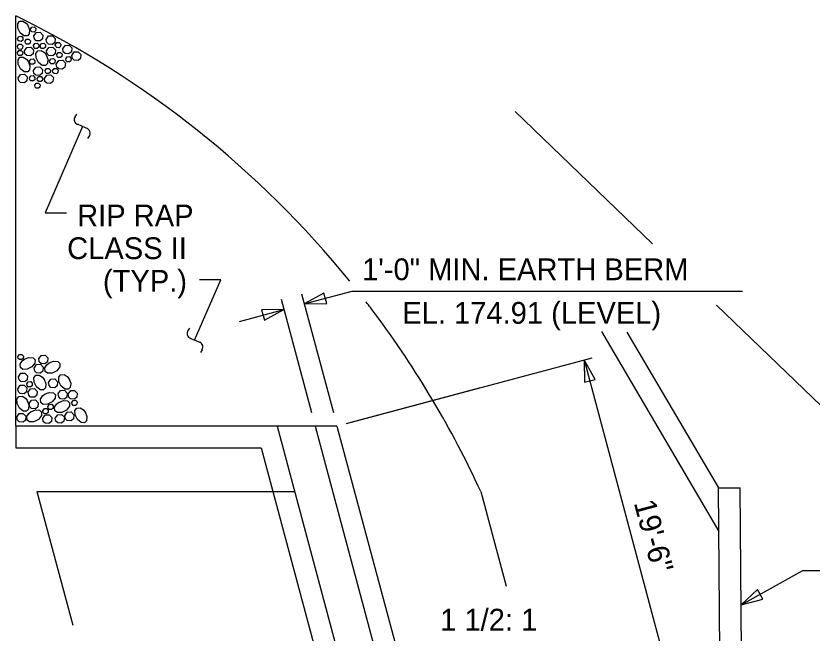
# Model space of a CAD drawing. Extents: x -20 to 509, y -659 to 21.
# Drawn here: x 57.47 to 94.05, y -95.57 to -67.25 of the extents above; entities that cross this region are included whole.
import ezdxf

# ---------------------------------------------------------------- set-up
doc = ezdxf.new("R2010")
doc.units = 0
for name, color, linetype in [('Arrowhead Terminators CELL', 7, 'Continuous'), ('Dimension Lines', 7, 'Continuous'), ('Exist Hydro Stream or Body of Water', 7, 'Continuous'), ('Exist Structure Major Bridge Seam', 7, 'Continuous'), ('Mis Object Lines', 7, 'Continuous'), ('Mis Object Lines Hidden', 7, 'Continuous'), ('Miscellaneous Lines CELL', 7, 'Continuous'), ('Sup Concrete Girder Lines', 7, 'Continuous'), ('Text', 7, 'Continuous')]:
    doc.layers.add(name, color=color, linetype=linetype)

msp = doc.modelspace()

# ---------------------------------------------------------------- linework, layer by layer
at = {"layer": 'Arrowhead Terminators CELL'}
for p, q in [((60.197, -71.878), (60.272, -71.752)), ((60.709, -72.397), (60.303, -72.221)), ((60.778, -72.876), (60.838, -72.784)), ((65.442, -81.57), (65.382, -81.662)), ((65.512, -82.049), (65.918, -82.224)), ((66.024, -82.567), (65.949, -82.694))]:
    msp.add_line(p, q, dxfattribs=at)
for points in [[(70.722, -80.467), (71.753, -80.449), (71.624, -79.966)], [(69.789, -80.717), (68.759, -80.734), (68.888, -81.217)], [(83.578, -83.03), (83.58, -83.114), (83.619, -83.103)], [(83.578, -83.03), (83.596, -84.061), (84.079, -83.931)], [(90.793, -94.277), (91.789, -94.011), (91.546, -93.574)]]:
    msp.add_lwpolyline(points, close=True, dxfattribs=at)
for centre, radius, start, end in [((60.373, -72.014), 0.221, 142.4705, 250.7561), ((60.637, -72.634), 0.249, 323.4021, 73.201), ((65.584, -81.811), 0.249, 143.4021, 253.201), ((65.847, -82.432), 0.221, 322.4705, 70.7561)]:
    msp.add_arc(centre, radius, start, end, dxfattribs=at)
at = {"layer": 'Dimension Lines'}
for p, q in [((60.536, -72.316), (58.823, -76.282)), ((58.823, -76.282), (59.794, -76.282)), ((65.685, -82.129), (66.883, -79.356)), ((66.883, -79.356), (65.911, -79.356)), ((70.598, -80.002), (72.058, -85.451)), ((70.722, -80.467), (72.926, -79.876)), ((72.926, -79.876), (90.848, -79.876)), ((69.665, -80.252), (71.057, -85.448)), ((67.742, -81.265), (69.789, -80.717)), ((72.661, -85.956), (83.942, -82.933)), ((83.578, -83.03), (88.262, -100.509)), ((72.875, -85.898), (78.772, -84.318)), ((90.793, -94.277), (93.629, -92.706)), ((93.629, -92.706), (95.304, -92.706))]:
    msp.add_line(p, q, dxfattribs=at)
at = {"layer": 'Exist Hydro Stream or Body of Water'}
for points in [[(86.72, -77.7), (80.409, -71.639)], [(97.738, -91.292), (97.285, -87.847), (89.653, -80.517)]]:
    msp.add_lwpolyline(points, dxfattribs=at)
at = {"layer": 'Exist Structure Major Bridge Seam'}
for p, q in [((84.37, -81.73), (89.763, -90.904)), ((85.546, -81.757), (89.745, -88.901)), ((89.745, -88.901), (90.745, -88.901)), ((89.892, -105.444), (89.745, -88.901)), ((90.898, -106.065), (90.745, -88.901))]:
    msp.add_line(p, q, dxfattribs=at)
at = {"layer": 'Mis Object Lines'}
for p, q in [((69.475, -86.072), (79.344, -122.906)), ((71.225, -86.072), (81.094, -122.906)), ((72.225, -86.072), (82.094, -122.906)), ((58.438, -89.072), (60.083, -95.211)), ((58.438, -89.072), (70.278, -89.072))]:
    msp.add_line(p, q, dxfattribs=at)
for points in [[(72.225, -86.072), (57.475, -86.072), (57.475, -87.072), (68.742, -87.072)], [(68.742, -87.072), (69.278, -89.072)]]:
    msp.add_lwpolyline(points, dxfattribs=at)
at = {"layer": 'Mis Object Lines Hidden'}
msp.add_lwpolyline([(69.278, -89.072), (77.54, -119.906)], dxfattribs=at)
at = {"layer": 'Miscellaneous Lines CELL'}
for points in [[(58.022, -67.668), (58.105, -67.878), (58.088, -68.071), (58.001, -68.162), (57.845, -68.159), (57.667, -68.02), (57.56, -67.806), (57.557, -67.603), (57.637, -67.49), (57.799, -67.479), (57.943, -67.571), (58.027, -67.677)], [(58.022, -67.668), (58.105, -67.878), (58.088, -68.071), (58.001, -68.162), (57.845, -68.159), (57.667, -68.02), (57.56, -67.806), (57.557, -67.603), (57.637, -67.49), (57.799, -67.479), (57.943, -67.571), (58.027, -67.677)], [(58.14, -67.85), (58.207, -67.755), (58.314, -67.748), (58.389, -67.826), (58.378, -67.934), (58.312, -67.989), (58.206, -67.982), (58.156, -67.933), (58.14, -67.85)], [(58.14, -67.85), (58.207, -67.755), (58.314, -67.748), (58.389, -67.826), (58.378, -67.934), (58.312, -67.989), (58.206, -67.982), (58.156, -67.933), (58.14, -67.85)], [(58.302, -68.163), (58.414, -68.004), (58.593, -67.993), (58.717, -68.122), (58.699, -68.303), (58.589, -68.395), (58.412, -68.382), (58.329, -68.301), (58.302, -68.163)], [(58.302, -68.163), (58.414, -68.004), (58.593, -67.993), (58.717, -68.122), (58.699, -68.303), (58.589, -68.395), (58.412, -68.382), (58.329, -68.301), (58.302, -68.163)], [(57.55, -68.279), (57.617, -68.183), (57.725, -68.177), (57.799, -68.255), (57.789, -68.363), (57.722, -68.418), (57.616, -68.411), (57.566, -68.362), (57.55, -68.279)], [(57.55, -68.279), (57.617, -68.183), (57.725, -68.177), (57.799, -68.255), (57.789, -68.363), (57.722, -68.418), (57.616, -68.411), (57.566, -68.362), (57.55, -68.279)], [(57.897, -68.407), (57.965, -68.311), (58.072, -68.305), (58.147, -68.382), (58.136, -68.491), (58.07, -68.546), (57.964, -68.538), (57.914, -68.49), (57.897, -68.407)], [(57.897, -68.407), (57.965, -68.311), (58.072, -68.305), (58.147, -68.382), (58.136, -68.491), (58.07, -68.546), (57.964, -68.538), (57.914, -68.49), (57.897, -68.407)], [(58.865, -68.326), (58.977, -68.166), (59.156, -68.156), (59.28, -68.285), (59.262, -68.466), (59.152, -68.558), (58.975, -68.545), (58.892, -68.464), (58.865, -68.326)], [(58.865, -68.326), (58.977, -68.166), (59.156, -68.156), (59.28, -68.285), (59.262, -68.466), (59.152, -68.558), (58.975, -68.545), (58.892, -68.464), (58.865, -68.326)], [(57.54, -68.64), (57.607, -68.544), (57.714, -68.538), (57.789, -68.615), (57.778, -68.724), (57.712, -68.779), (57.606, -68.771), (57.556, -68.723), (57.54, -68.64)], [(57.54, -68.64), (57.607, -68.544), (57.714, -68.538), (57.789, -68.615), (57.778, -68.724), (57.712, -68.779), (57.606, -68.771), (57.556, -68.723), (57.54, -68.64)], [(57.863, -68.847), (57.975, -68.688), (58.154, -68.678), (58.278, -68.806), (58.26, -68.987), (58.15, -69.079), (57.973, -69.066), (57.89, -68.986), (57.863, -68.847)], [(57.863, -68.847), (57.975, -68.688), (58.154, -68.678), (58.278, -68.806), (58.26, -68.987), (58.15, -69.079), (57.973, -69.066), (57.89, -68.986), (57.863, -68.847)], [(58.283, -68.602), (58.35, -68.506), (58.458, -68.5), (58.532, -68.577), (58.522, -68.686), (58.455, -68.741), (58.349, -68.733), (58.299, -68.685), (58.283, -68.602)], [(58.283, -68.602), (58.35, -68.506), (58.458, -68.5), (58.532, -68.577), (58.522, -68.686), (58.455, -68.741), (58.349, -68.733), (58.299, -68.685), (58.283, -68.602)], [(58.587, -68.602), (58.654, -68.506), (58.762, -68.5), (58.836, -68.577), (58.826, -68.686), (58.759, -68.741), (58.653, -68.733), (58.603, -68.685), (58.587, -68.602)], [(58.587, -68.602), (58.654, -68.506), (58.762, -68.5), (58.836, -68.577), (58.826, -68.686), (58.759, -68.741), (58.653, -68.733), (58.603, -68.685), (58.587, -68.602)], [(58.882, -68.847), (58.994, -68.688), (59.173, -68.678), (59.297, -68.806), (59.279, -68.987), (59.169, -69.079), (58.992, -69.066), (58.909, -68.986), (58.882, -68.847)], [(58.882, -68.847), (58.994, -68.688), (59.173, -68.678), (59.297, -68.806), (59.279, -68.987), (59.169, -69.079), (58.992, -69.066), (58.909, -68.986), (58.882, -68.847)], [(59.285, -68.566), (59.352, -68.47), (59.459, -68.464), (59.534, -68.541), (59.523, -68.65), (59.457, -68.705), (59.351, -68.697), (59.301, -68.649), (59.285, -68.566)], [(59.285, -68.566), (59.352, -68.47), (59.459, -68.464), (59.534, -68.541), (59.523, -68.65), (59.457, -68.705), (59.351, -68.697), (59.301, -68.649), (59.285, -68.566)], [(59.624, -68.758), (59.737, -68.598), (59.915, -68.588), (60.04, -68.717), (60.022, -68.898), (59.911, -68.99), (59.735, -68.977), (59.652, -68.896), (59.625, -68.758)], [(59.624, -68.758), (59.737, -68.598), (59.915, -68.588), (60.04, -68.717), (60.022, -68.898), (59.911, -68.99), (59.735, -68.977), (59.652, -68.896), (59.625, -68.758)], [(57.54, -68.93), (57.607, -68.834), (57.714, -68.828), (57.789, -68.905), (57.778, -69.014), (57.712, -69.069), (57.606, -69.061), (57.556, -69.013), (57.54, -68.93)], [(57.54, -68.93), (57.607, -68.834), (57.714, -68.828), (57.789, -68.905), (57.778, -69.014), (57.712, -69.069), (57.606, -69.061), (57.556, -69.013), (57.54, -68.93)], [(58.86, -69.028), (58.943, -69.237), (58.927, -69.43), (58.84, -69.521), (58.683, -69.519), (58.506, -69.38), (58.398, -69.165), (58.395, -68.963), (58.476, -68.849), (58.637, -68.838), (58.781, -68.93), (58.865, -69.036)], [(58.86, -69.028), (58.943, -69.237), (58.927, -69.43), (58.84, -69.521), (58.683, -69.519), (58.506, -69.38), (58.398, -69.165), (58.395, -68.963), (58.476, -68.849), (58.637, -68.838), (58.781, -68.93), (58.865, -69.036)], [(59.349, -69.021), (59.416, -68.926), (59.524, -68.92), (59.598, -68.997), (59.588, -69.105), (59.521, -69.161), (59.415, -69.153), (59.365, -69.105), (59.349, -69.021)], [(59.349, -69.021), (59.416, -68.926), (59.524, -68.92), (59.598, -68.997), (59.588, -69.105), (59.521, -69.161), (59.415, -69.153), (59.365, -69.105), (59.349, -69.021)], [(59.76, -69.217), (59.827, -69.121), (59.935, -69.115), (60.009, -69.192), (59.998, -69.301), (59.932, -69.356), (59.826, -69.348), (59.776, -69.3), (59.76, -69.217)], [(59.76, -69.217), (59.827, -69.121), (59.935, -69.115), (60.009, -69.192), (59.998, -69.301), (59.932, -69.356), (59.826, -69.348), (59.776, -69.3), (59.76, -69.217)], [(60.04, -69.059), (60.152, -68.9), (60.331, -68.89), (60.456, -69.019), (60.438, -69.199), (60.327, -69.291), (60.15, -69.279), (60.067, -69.198), (60.04, -69.059)], [(60.04, -69.059), (60.152, -68.9), (60.331, -68.89), (60.456, -69.019), (60.438, -69.199), (60.327, -69.291), (60.15, -69.279), (60.067, -69.198), (60.04, -69.059)], [(58.037, -69.324), (58.12, -69.534), (58.103, -69.726), (58.016, -69.818), (57.86, -69.815), (57.682, -69.676), (57.575, -69.461), (57.571, -69.259), (57.652, -69.145), (57.813, -69.134), (57.958, -69.227), (58.042, -69.333)], [(58.037, -69.324), (58.12, -69.534), (58.103, -69.726), (58.016, -69.818), (57.86, -69.815), (57.682, -69.676), (57.575, -69.461), (57.571, -69.259), (57.652, -69.145), (57.813, -69.134), (57.958, -69.227), (58.042, -69.333)], [(58.1, -69.323), (58.167, -69.228), (58.274, -69.222), (58.349, -69.299), (58.338, -69.407), (58.272, -69.462), (58.166, -69.455), (58.116, -69.406), (58.1, -69.323)], [(58.1, -69.323), (58.167, -69.228), (58.274, -69.222), (58.349, -69.299), (58.338, -69.407), (58.272, -69.462), (58.166, -69.455), (58.116, -69.406), (58.1, -69.323)], [(59.024, -69.305), (59.091, -69.21), (59.199, -69.204), (59.273, -69.281), (59.263, -69.389), (59.196, -69.444), (59.09, -69.437), (59.04, -69.388), (59.024, -69.305)], [(59.024, -69.305), (59.091, -69.21), (59.199, -69.204), (59.273, -69.281), (59.263, -69.389), (59.196, -69.444), (59.09, -69.437), (59.04, -69.388), (59.024, -69.305)], [(59.331, -69.452), (59.443, -69.292), (59.622, -69.282), (59.746, -69.411), (59.728, -69.592), (59.617, -69.684), (59.441, -69.671), (59.358, -69.59), (59.331, -69.452)], [(59.331, -69.452), (59.443, -69.292), (59.622, -69.282), (59.746, -69.411), (59.728, -69.592), (59.617, -69.684), (59.441, -69.671), (59.358, -69.59), (59.331, -69.452)], [(58.276, -69.751), (58.388, -69.591), (58.567, -69.581), (58.691, -69.71), (58.673, -69.891), (58.562, -69.983), (58.386, -69.97), (58.303, -69.889), (58.276, -69.751)], [(58.276, -69.751), (58.388, -69.591), (58.567, -69.581), (58.691, -69.71), (58.673, -69.891), (58.562, -69.983), (58.386, -69.97), (58.303, -69.889), (58.276, -69.751)], [(58.815, -69.753), (58.883, -69.657), (58.99, -69.651), (59.065, -69.729), (59.054, -69.837), (58.987, -69.892), (58.881, -69.885), (58.832, -69.836), (58.815, -69.753)], [(58.815, -69.753), (58.883, -69.657), (58.99, -69.651), (59.065, -69.729), (59.054, -69.837), (58.987, -69.892), (58.881, -69.885), (58.832, -69.836), (58.815, -69.753)], [(59.16, -69.758), (59.227, -69.662), (59.335, -69.656), (59.409, -69.733), (59.398, -69.842), (59.332, -69.897), (59.226, -69.889), (59.176, -69.841), (59.16, -69.758)], [(59.16, -69.758), (59.227, -69.662), (59.335, -69.656), (59.409, -69.733), (59.398, -69.842), (59.332, -69.897), (59.226, -69.889), (59.176, -69.841), (59.16, -69.758)], [(57.578, -70.089), (57.69, -69.929), (57.869, -69.919), (57.993, -70.048), (57.975, -70.229), (57.865, -70.321), (57.688, -70.308), (57.605, -70.227), (57.578, -70.089)], [(57.578, -70.089), (57.69, -69.929), (57.869, -69.919), (57.993, -70.048), (57.975, -70.229), (57.865, -70.321), (57.688, -70.308), (57.605, -70.227), (57.578, -70.089)], [(58.1, -70.088), (58.167, -69.993), (58.274, -69.986), (58.349, -70.064), (58.338, -70.172), (58.272, -70.227), (58.166, -70.22), (58.116, -70.171), (58.1, -70.088)], [(58.1, -70.088), (58.167, -69.993), (58.274, -69.986), (58.349, -70.064), (58.338, -70.172), (58.272, -70.227), (58.166, -70.22), (58.116, -70.171), (58.1, -70.088)], [(58.454, -70.121), (58.521, -70.026), (58.628, -70.02), (58.703, -70.097), (58.692, -70.205), (58.626, -70.261), (58.52, -70.253), (58.47, -70.205), (58.454, -70.121)], [(58.454, -70.121), (58.521, -70.026), (58.628, -70.02), (58.703, -70.097), (58.692, -70.205), (58.626, -70.261), (58.52, -70.253), (58.47, -70.205), (58.454, -70.121)], [(58.78, -70.119), (58.892, -69.959), (59.071, -69.949), (59.195, -70.078), (59.177, -70.259), (59.067, -70.35), (58.89, -70.338), (58.807, -70.257), (58.78, -70.119)], [(58.78, -70.119), (58.892, -69.959), (59.071, -69.949), (59.195, -70.078), (59.177, -70.259), (59.067, -70.35), (58.89, -70.338), (58.807, -70.257), (58.78, -70.119)], [(58.339, -70.426), (58.406, -70.33), (58.514, -70.324), (58.588, -70.401), (58.578, -70.51), (58.511, -70.565), (58.405, -70.557), (58.355, -70.509), (58.339, -70.426)], [(58.339, -70.426), (58.406, -70.33), (58.514, -70.324), (58.588, -70.401), (58.578, -70.51), (58.511, -70.565), (58.405, -70.557), (58.355, -70.509), (58.339, -70.426)], [(57.567, -82.882), (57.635, -82.787), (57.742, -82.78), (57.817, -82.858), (57.806, -82.966), (57.739, -83.021), (57.633, -83.014), (57.584, -82.965), (57.567, -82.882)], [(57.858, -83.005), (58.067, -82.922), (58.26, -82.938), (58.351, -83.025), (58.348, -83.182), (58.21, -83.359), (57.995, -83.467), (57.793, -83.47), (57.679, -83.389), (57.668, -83.228), (57.76, -83.084), (57.866, -83)], [(58.522, -82.985), (58.634, -82.825), (58.813, -82.815), (58.937, -82.944), (58.919, -83.125), (58.808, -83.216), (58.632, -83.204), (58.549, -83.123), (58.522, -82.985)], [(58.311, -83.406), (58.423, -83.247), (58.602, -83.237), (58.726, -83.366), (58.708, -83.546), (58.598, -83.638), (58.421, -83.625), (58.338, -83.545), (58.311, -83.406)], [(58.996, -83.174), (59.206, -83.091), (59.399, -83.108), (59.49, -83.195), (59.487, -83.351), (59.348, -83.529), (59.134, -83.636), (58.931, -83.64), (58.818, -83.559), (58.807, -83.398), (58.899, -83.253), (59.005, -83.169)], [(57.592, -83.806), (57.704, -83.647), (57.883, -83.637), (58.008, -83.765), (57.99, -83.946), (57.879, -84.038), (57.702, -84.025), (57.619, -83.945), (57.592, -83.806)], [(58.768, -83.919), (58.852, -84.128), (58.835, -84.321), (58.748, -84.412), (58.592, -84.409), (58.414, -84.271), (58.307, -84.056), (58.303, -83.854), (58.384, -83.74), (58.545, -83.729), (58.689, -83.821), (58.774, -83.927)], [(59.907, -83.892), (59.99, -84.101), (59.974, -84.294), (59.887, -84.385), (59.73, -84.382), (59.553, -84.243), (59.446, -84.029), (59.442, -83.826), (59.523, -83.713), (59.684, -83.702), (59.828, -83.794), (59.913, -83.9)], [(57.977, -84.133), (58.044, -84.037), (58.152, -84.031), (58.226, -84.108), (58.216, -84.217), (58.149, -84.272), (58.043, -84.264), (57.993, -84.216), (57.977, -84.133)], [(58.97, -84.077), (59.082, -83.918), (59.261, -83.908), (59.385, -84.037), (59.367, -84.217), (59.257, -84.309), (59.08, -84.296), (58.997, -84.216), (58.97, -84.077)], [(57.561, -84.36), (57.673, -84.2), (57.852, -84.19), (57.976, -84.319), (57.958, -84.5), (57.848, -84.592), (57.671, -84.579), (57.588, -84.498), (57.561, -84.36)], [(58.034, -84.518), (58.146, -84.358), (58.325, -84.348), (58.45, -84.477), (58.432, -84.658), (58.321, -84.75), (58.144, -84.737), (58.061, -84.656), (58.034, -84.518)], [(59.418, -84.597), (59.53, -84.437), (59.709, -84.427), (59.833, -84.556), (59.815, -84.737), (59.705, -84.829), (59.528, -84.816), (59.445, -84.735), (59.418, -84.597)], [(59.879, -84.604), (59.991, -84.444), (60.17, -84.434), (60.294, -84.563), (60.276, -84.744), (60.166, -84.836), (59.989, -84.823), (59.906, -84.742), (59.879, -84.604)], [(57.989, -84.895), (58.072, -85.104), (58.055, -85.297), (57.968, -85.388), (57.812, -85.385), (57.635, -85.247), (57.527, -85.032), (57.524, -84.83), (57.605, -84.716), (57.766, -84.705), (57.91, -84.797), (57.994, -84.903)], [(58.793, -84.611), (59.003, -84.528), (59.195, -84.545), (59.287, -84.632), (59.284, -84.788), (59.145, -84.966), (58.93, -85.073), (58.728, -85.077), (58.614, -84.996), (58.603, -84.835), (58.696, -84.69), (58.802, -84.606)], [(58.084, -85.042), (58.196, -84.883), (58.375, -84.873), (58.499, -85.002), (58.481, -85.182), (58.371, -85.274), (58.194, -85.261), (58.111, -85.181), (58.084, -85.042)], [(58.944, -85.173), (59.011, -85.077), (59.119, -85.071), (59.193, -85.149), (59.182, -85.257), (59.116, -85.312), (59.01, -85.304), (58.96, -85.256), (58.944, -85.173)], [(59.443, -84.986), (59.653, -84.903), (59.846, -84.919), (59.937, -85.006), (59.934, -85.163), (59.795, -85.34), (59.581, -85.447), (59.378, -85.451), (59.264, -85.37), (59.254, -85.209), (59.346, -85.065), (59.452, -84.98)], [(60.042, -84.989), (60.109, -84.893), (60.217, -84.887), (60.291, -84.965), (60.28, -85.073), (60.214, -85.128), (60.108, -85.121), (60.058, -85.072), (60.042, -84.989)], [(57.516, -85.659), (57.628, -85.499), (57.807, -85.489), (57.932, -85.618), (57.914, -85.799), (57.803, -85.89), (57.626, -85.878), (57.543, -85.797), (57.516, -85.659)], [(58.162, -85.413), (58.372, -85.33), (58.565, -85.346), (58.656, -85.433), (58.653, -85.59), (58.514, -85.767), (58.3, -85.874), (58.097, -85.878), (57.984, -85.797), (57.973, -85.636), (58.065, -85.492), (58.171, -85.407)], [(58.705, -85.718), (58.817, -85.558), (58.996, -85.548), (59.121, -85.677), (59.103, -85.858), (58.992, -85.95), (58.815, -85.937), (58.732, -85.856), (58.705, -85.718)], [(58.713, -85.367), (58.78, -85.272), (58.887, -85.266), (58.962, -85.343), (58.951, -85.451), (58.885, -85.507), (58.779, -85.499), (58.729, -85.451), (58.713, -85.367)], [(59.283, -85.711), (59.395, -85.552), (59.574, -85.541), (59.699, -85.67), (59.681, -85.851), (59.57, -85.943), (59.394, -85.93), (59.31, -85.85), (59.284, -85.711)], [(59.718, -85.594), (59.83, -85.435), (60.009, -85.425), (60.133, -85.554), (60.115, -85.734), (60.005, -85.826), (59.828, -85.813), (59.745, -85.733), (59.718, -85.594)], [(60.653, -85.423), (60.736, -85.633), (60.719, -85.826), (60.632, -85.917), (60.476, -85.914), (60.298, -85.775), (60.191, -85.561), (60.188, -85.358), (60.268, -85.244), (60.43, -85.234), (60.574, -85.326), (60.658, -85.432)]]:
    msp.add_lwpolyline(points, dxfattribs=at)
at = {"layer": 'Sup Concrete Girder Lines'}
for p, q in [((57.475, -86.072), (57.475, -67.246)), ((57.475, -86.072), (57.475, -67.246)), ((78.826, -89.072), (79.99, -93.417))]:
    msp.add_line(p, q, dxfattribs=at)
for start, end in [(39.1222, 64.0036), (36.716, 37.582), (24.7352, 36.716)]:
    msp.add_arc((37.56, -108.084), 45.435, start, end, dxfattribs=at)

# ---------------------------------------------------------------- texts
at = {"layer": 'Text'}
for s, p in [('RIP RAP', (60.286, -76.907)), ('CLASS II', (59.829, -78.407)), ('1\'-0" MIN. EARTH BERM', (73.377, -79.376)), ('(TYP.)', (61.471, -79.907)), ('EL. 174.91 (LEVEL)', (75.223, -81.376)), ('1 1/2: 1', (76.965, -95.458)), ('1 1/2: 1', (76.965, -95.458))]:
    msp.add_text(s, height=1, dxfattribs=at).set_placement(p)
msp.add_text('19\'-6"', height=1, rotation=285, dxfattribs=at).set_placement((85.855, -89.595))

doc.saveas('drawing.dxf')
